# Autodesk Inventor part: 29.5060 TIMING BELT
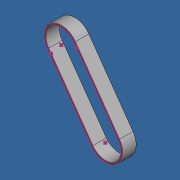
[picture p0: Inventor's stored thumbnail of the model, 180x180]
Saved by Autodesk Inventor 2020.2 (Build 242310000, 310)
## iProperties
Created: 2020-08
Part Number: 29.5060 TIMING BELT
Material: Generic
Document SubType Name: Modeling
Designer: amoles
Density: 1 g/cm^3
Appearance: Default
Author: amoles
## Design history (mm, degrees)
sketch "Sketch1"
  geometry: L1 (71.217, -172.387)-(-33.783, -23.887); L2 (33.783, 23.887)-(138.783, -124.613); L3 (75.299, -169.5)-(-29.701, -21); L4 (29.701, 21)-(134.701, -127.5); C1 r 10 at (105, -148.5) reference; A1 r 36.375 centre (0, 0) between (-11.651, 34.459) and (-15.096, 33.095) reference; A2 r 36.375 centre (105, -148.5) between (103.147, -184.828) and (106.853, -184.828) reference; A3 r 36.375 centre (105, -148.5) between (75.299, -169.5) and (134.701, -127.5); A4 r 36.375 centre (0, 0) between (-11.651, 34.459) and (-29.701, -21); A5 r 41.375 centre (105, -148.5) between (71.217, -172.387) and (138.783, -124.613); A6 r 41.375 centre (0, 0) between (-33.783, -23.887) and (33.783, 23.887); 4 further points
  constraints: 9 point on circle, 8 end point, 7 tangent, 4 centre point, 4 coincident, 1 concentric, 1 parallel
  dimensions: "d0" = 5 radial gap between concentric circles of A4 A6; "d1" = 5 radial gap between concentric circles of A3 A5
extrude "Extrusion1" new body sketch "Sketch1" stored distance "d2" = 32; taper "d3" = 0 deg
sketch "Sketch3"
  geometry: L1 (75.299, -169.5)-(-29.701, -21) reference; L2 (29.701, 21)-(134.701, -127.5) reference; L3 (35.334, 15.17)-(33.994, 14.928) reference; L4 (36.953, 10.743)-(37.629, 11.925) reference; L5 (-25.407, -27.073)-(-26.082, -28.255) reference; L6 (-23.788, -31.5)-(-22.448, -31.258) reference; A1 r 2.193 centre (35.725, 13.013) between (37.629, 11.925) and (35.334, 15.17) reference; A2 r 2.193 centre (-24.178, -29.343) between (-26.082, -28.255) and (-23.788, -31.5) reference; 2 further points
extrude "Extrusion2" cut sketch "Sketch3" extent not by distance; stored distance "d4" = 0; taper "d5" = 0 deg
body "Solid1"
pattern_linear "Rectangular Pattern1" dims "d8" = 10
node "Reference1"
node "Reference2"
node "Reference3"
node "Reference4"
node "Reference5"
node "Reference6"
node "Reference7"
node "Reference8"
node "Reference9"
